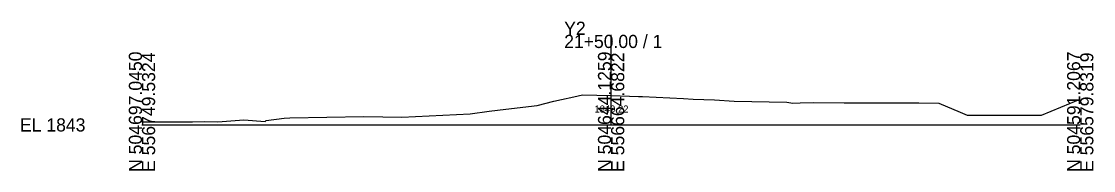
# Model space of a CAD drawing. Extents: x -26 to 1503, y -10 to 3574.
# Drawn here: x -25.7 to 202.8, y 1490.3 to 1522 of the extents above; entities that cross this region are included whole.
import ezdxf

# ---------------------------------------------------------------- set-up
doc = ezdxf.new("R2010")
doc.units = 0
for name, color, linetype in [('Default', 7, 'Continuous'), ('Exist Cross Section Cell', 7, 'Continuous'), ('Exist XS Center Line Elevation Label', 7, 'Continuous'), ('Exist XS Ground Line', 7, 'Continuous')]:
    doc.layers.add(name, color=color, linetype=linetype)

msp = doc.modelspace()

# ---------------------------------------------------------------- linework, layer by layer
at = {"layer": 'Exist Cross Section Cell'}
for p, q in [((100, 1500), (100, 1519.15)), ((0, 1500), (100, 1500)), ((100, 1500), (200, 1500))]:
    msp.add_line(p, q, dxfattribs=at)
at = {"layer": 'Exist XS Ground Line'}
for p, q in [((92.03, 1505.97), (93.89, 1506.38)), ((93.89, 1506.38), (100, 1506.22)), ((100, 1506.22), (105.83, 1506.07)), ((105.83, 1506.07), (106.69, 1506.03)), ((77.57, 1503.37), (84.22, 1504.13)), ((84.22, 1504.13), (87.78, 1505.03)), ((87.78, 1505.03), (89.45, 1505.4)), ((89.45, 1505.4), (92.03, 1505.97)), ((106.69, 1506.03), (115.43, 1505.65)), ((115.43, 1505.65), (117.46, 1505.51)), ((117.46, 1505.51), (122.01, 1505.31)), ((122.01, 1505.31), (126.23, 1505.03)), ((126.23, 1505.03), (137.44, 1504.85)), ((137.44, 1504.85), (138.73, 1504.61)), ((138.73, 1504.61), (140.27, 1504.68)), ((140.27, 1504.68), (143.12, 1504.79)), ((143.12, 1504.79), (149.7, 1504.69)), ((149.7, 1504.69), (154.57, 1504.7)), ((154.57, 1504.7), (162.66, 1504.66)), ((162.66, 1504.66), (165.56, 1504.68)), ((165.56, 1504.68), (169.83, 1504.64)), ((169.83, 1504.64), (174.39, 1502.74)), ((191.72, 1502.1), (200, 1505.47)), ((30.28, 1501.45), (31.53, 1501.49)), ((31.53, 1501.49), (47.26, 1501.76)), ((47.26, 1501.76), (55.39, 1501.62)), ((55.39, 1501.62), (69.99, 1502.36)), ((69.99, 1502.36), (74.02, 1502.92)), ((74.02, 1502.92), (77.57, 1503.37)), ((174.39, 1502.74), (175.87, 1502.05)), ((175.87, 1502.05), (178.43, 1502.06)), ((178.43, 1502.06), (184.44, 1502.07)), ((184.44, 1502.07), (191.72, 1502.1)), ((0, 1500.69), (10.74, 1500.66)), ((10.74, 1500.66), (13.25, 1500.73)), ((13.25, 1500.73), (16.17, 1500.67)), ((16.17, 1500.67), (21.68, 1501.07)), ((21.68, 1501.07), (26.25, 1500.74)), ((26.25, 1500.74), (26.49, 1500.94)), ((26.49, 1500.94), (30.28, 1501.45))]:
    msp.add_line(p, q, dxfattribs=at)

# ---------------------------------------------------------------- texts
at = {"layer": 'Default'}
msp.add_text('-', height=0.0001, dxfattribs=at).set_placement((0, 1500))
at = {"layer": 'Exist Cross Section Cell'}
for s, p in [('Y2', (90, 1519.15)), ('21+50.00 / 1', (90, 1516.35)), ('EL 1843', (-26, 1498.6))]:
    msp.add_text(s, height=2.8, dxfattribs=at).set_placement(p)
for s, p in [('N 504697.0450', (0, 1490)), ('E 556749.5324', (2.8, 1490)), ('N 504644.1259', (100, 1490)), ('E 556664.6822', (102.8, 1490)), ('N 504591.2067', (200, 1490)), ('E 556579.8319', (202.8, 1490))]:
    msp.add_text(s, height=2.8, rotation=90, dxfattribs=at).set_placement(p)
at = {"layer": 'Exist XS Center Line Elevation Label'}
msp.add_text('1849.22', height=1.5, dxfattribs=at).set_placement((96.45, 1502.63))

doc.saveas('drawing.dxf')
